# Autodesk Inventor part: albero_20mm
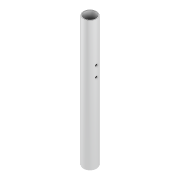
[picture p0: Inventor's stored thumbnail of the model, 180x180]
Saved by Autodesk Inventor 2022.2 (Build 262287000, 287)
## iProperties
Created: 2025-03
Part Number: albero_20mm
Material: Generico
Document SubType Name: Modeling
Designer: 18907419
Density: 1 g/cm^3
Appearance: Alluminio - Piatto
Author: 18907419
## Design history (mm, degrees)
sketch "Schizzo1"
  geometry: C1 r 10 at (0, 0); C2 r 9 at (0, 0); 1 further point
  constraints: 2 centre point, 1 coincident
  dimensions: "d0" = 20 diameter of C1; "d1" = 1 radial gap between concentric circles of C1 C2
extrude "Estrusione1" new body sketch "Schizzo1" distance "d2" = 200; taper "d3" = 0 deg
sketch "Schizzo2"
  geometry: C1 r 1.7 at (138, 0) reference; C2 r 1.7 at (122, 0) reference; 1 further point
extrude "Estrusione2" cut sketch "Schizzo2" stored distance "d4" = 200; taper "d5" = 0 deg
node "Solido1"
node "Riferimento1"
node "Riferimento2"
